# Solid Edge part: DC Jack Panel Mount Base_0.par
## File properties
Last saved by: morva
Revision: 76
Accuracy: 0.990
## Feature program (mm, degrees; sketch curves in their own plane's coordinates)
body "unnamed Body 1"
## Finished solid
Body 1: solid body, 132 faces, 363 edges, 234 vertices.
  Faces by surface: plane 46, spline 43, cylinder 38, torus 4, cone 1
  Edges by curve: line 144, spline 78, curve on surface 53, circle 44, intersection 44
Bounding box of the edges (mm; curved faces can reach further): 10.200 x 10.200 x 17.630, from (-5.1, -5.1, -16.83) to (5.1, 5.1, 0.8).
Cylindrical faces by radius (mm): R0.45 x1, R0.55 x1, R0.825 x1, R1.05 x1, R1.1 x4, R1.46 x1, R2.8 x1, R3.4 x1, R3.55 x1, R3.552 x12, R3.8 x12, R4.41 x1, R5.1 x1
Conical faces (half-angle, radius in mm at the cone's reference point): 31.3832 deg R2.8 x1
Toroidal faces (ring radius, tube radius in mm): R0.05 r1 x1, R0.725 r0.1 x1, R0.925 r0.1 x1, R3.7 r0.1 x1
Planar faces by outward normal: +x 3, +y 7, +z 8, -x 3, -y 7, -z 14, oblique 4
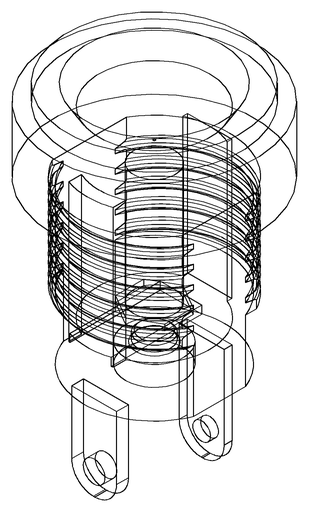
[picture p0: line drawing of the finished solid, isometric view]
